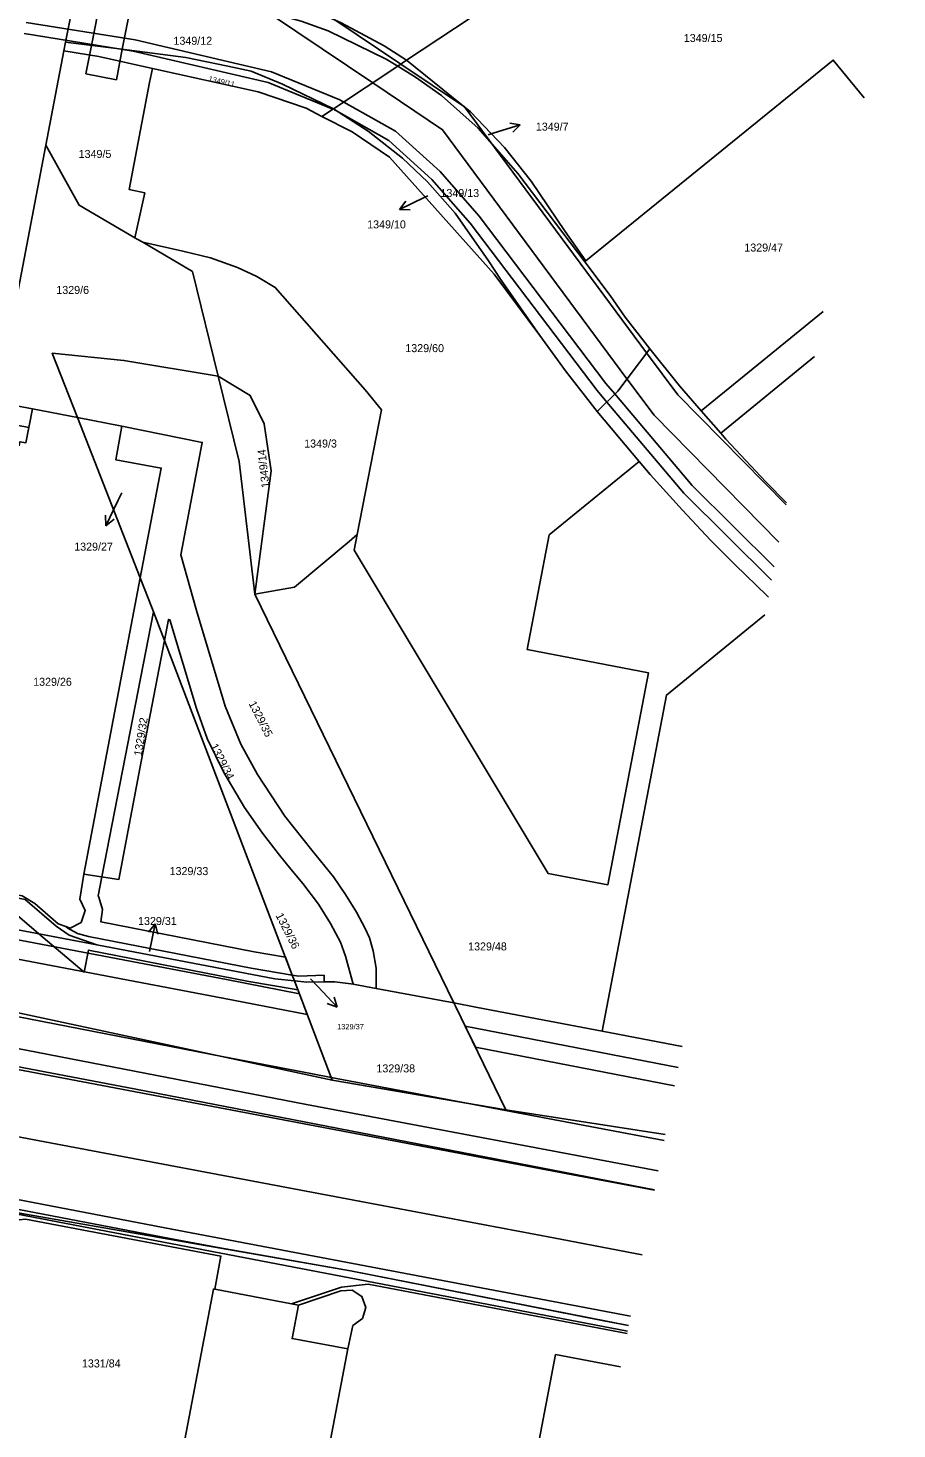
# Model space of a CAD drawing. Extents: x -601602 to -600882, y -1162594 to -1161950.
# Drawn here: x -600985.6 to -600893.3, y -1162422.3 to -1162273.6 of the extents above; entities that cross this region are included whole.
import ezdxf

# ---------------------------------------------------------------- set-up
doc = ezdxf.new("R2010")
doc.units = 0
for name, color, linetype in [('KN_Hranice parcel', 7, 'Continuous'), ('KN_Parcelní čísla', 7, 'Continuous'), ('KN_Pop  PČ popisy', 7, 'Continuous'), ('KN_Vnitřní kresba', 7, 'Continuous'), ('KN_Věcná břemena k části', 7, 'Continuous')]:
    doc.layers.add(name, color=color, linetype=linetype)

# ---------------------------------------------------------------- blocks, each defined once
blk = doc.blocks.new('1029_19')
at = {"layer": 'KN_Pop  PČ popisy'}
for p, q in [((0, 0), (-2.7, -1.32)), ((-2.7, -1.32), (-2.02, -0.43)), ((-2.7, -1.32), (-1.58, -1.33))]:
    blk.add_line(p, q, dxfattribs=at)
blk = doc.blocks.new('1029_44')
at = {"layer": 'KN_Pop  PČ popisy'}
for p, q in [((0, 0), (2.87, 0.88)), ((2.87, 0.88), (1.77, 1.06)), ((2.87, 0.88), (2.06, 0.11))]:
    blk.add_line(p, q, dxfattribs=at)
blk = doc.blocks.new('1029_53')
at = {"layer": 'KN_Pop  PČ popisy'}
for p, q in [((0, 0), (-1.32, -2.7)), ((-1.32, -2.7), (-1.33, -1.58)), ((-1.32, -2.7), (-0.43, -2.02))]:
    blk.add_line(p, q, dxfattribs=at)
blk = doc.blocks.new('1029_55')
at = {"layer": 'KN_Pop  PČ popisy'}
for p, q in [((0.57, 2.95), (-0.11, 2.06)), ((0, 0), (0.57, 2.95)), ((0.57, 2.95), (0.87, 1.87))]:
    blk.add_line(p, q, dxfattribs=at)
blk = doc.blocks.new('1029_56')
at = {"layer": 'KN_Pop  PČ popisy'}
for p, q in [((0, 0), (2.05, -2.19)), ((2.05, -2.19), (1.73, -1.12)), ((2.05, -2.19), (1, -1.8))]:
    blk.add_line(p, q, dxfattribs=at)

msp = doc.modelspace()

# ---------------------------------------------------------------- linework, layer by layer
at = {"layer": 'KN_Hranice parcel'}
for p, q in [((-600945.37, -1162276.99), (-600893.29, -1162242.43)), ((-600980.13, -1162267.57), (-600981.57, -1162275.06)), ((-600981.57, -1162275.06), (-600981.75, -1162275.98)), ((-600981.75, -1162275.98), (-600983.66, -1162285.99)), ((-600953.14, -1162282.15), (-600946.31, -1162277.62)), ((-600946.31, -1162277.62), (-600945.37, -1162276.99)), ((-600954.35, -1162282.95), (-600953.14, -1162282.15)), ((-600926.45, -1162298.39), (-600926.33, -1162298.3)), ((-600902.05, -1162308.45), (-600912.01, -1162316.57)), ((-600985.1, -1162314), (-600980.31, -1162314.93)), ((-600973.64, -1162331.94), (-600980.31, -1162314.93)), ((-600975.59, -1162315.84), (-600980.31, -1162314.93)), ((-600925.11, -1162314.27), (-600920.66, -1162319.58)), ((-600912.01, -1162316.57), (-600914.07, -1162314.2)), ((-600979.64, -1162363.4), (-600973.64, -1162331.94)), ((-600940.35, -1162377.09), (-600961.49, -1162333.68)), ((-600957.51, -1162374.13), (-600971.07, -1162338.59)), ((-600978.24, -1162370.92), (-600996.38, -1162367.46)), ((-600957.28, -1162374.74), (-600957.51, -1162374.13)), ((-600953.26, -1162385.27), (-600957.28, -1162374.74)), ((-600951.03, -1162375.09), (-600948.58, -1162375.55)), ((-600948.58, -1162375.55), (-600940.35, -1162377.09)), ((-600924.6, -1162380.1), (-600916.11, -1162381.72)), ((-600953.26, -1162385.27), (-600934.82, -1162388.45)), ((-600996.34, -1162397.68), (-600951.33, -1162405.52)), ((-600951.33, -1162405.52), (-600921.8, -1162411.34)), ((-600957.58, -1162409.04), (-600965.74, -1162407.49))]:
    msp.add_line(p, q, dxfattribs=at)
for points in [[(-600980.13, -1162267.57), (-600975.78, -1162268.36), (-600962.15, -1162271.32), (-600956.57, -1162272.84), (-600953.71, -1162273.86), (-600947.53, -1162276.88), (-600946.31, -1162277.62)], [(-600945.37, -1162276.99), (-600947.74, -1162275.47), (-600952.3, -1162273), (-600955.63, -1162271.53), (-600961.13, -1162269.66), (-600963.68, -1162269.01), (-600969.05, -1162268.07), (-600976.58, -1162267.13), (-600979.49, -1162266.77)], [(-600981.57, -1162275.06), (-600975.88, -1162275.78), (-600968.82, -1162276.68), (-600964.35, -1162277.6), (-600961.88, -1162278.16), (-600958.54, -1162279.52), (-600953.14, -1162282.15)], [(-600972.33, -1162277.85), (-600978.05, -1162276.59), (-600981.75, -1162275.98)], [(-600974.22, -1162295.84), (-600973.17, -1162291.07), (-600974.83, -1162290.7), (-600972.68, -1162279.36), (-600972.33, -1162277.85)], [(-600972.33, -1162277.85), (-600961.14, -1162280.33), (-600956.03, -1162282.09), (-600954.35, -1162282.95)], [(-600946.31, -1162277.62), (-600944.41, -1162278.77), (-600941.67, -1162280.74), (-600937.78, -1162284.21), (-600933.54, -1162289.01), (-600926.45, -1162298.39)], [(-600926.33, -1162298.3), (-600928.53, -1162295.18), (-600932.12, -1162289.81), (-600934.95, -1162286.26), (-600938.57, -1162282.47), (-600945.37, -1162276.99)], [(-600926.33, -1162298.3), (-600900.05, -1162276.97), (-600896.78, -1162280.98)], [(-600953.14, -1162282.15), (-600949.43, -1162284.52), (-600945.8, -1162287.38), (-600943.14, -1162289.9), (-600940.21, -1162293.21), (-600936.66, -1162298.28), (-600935.31, -1162300.33), (-600931.23, -1162306.23)], [(-600954.35, -1162282.95), (-600951.14, -1162284.6), (-600947.18, -1162287.26), (-600936.08, -1162299.69), (-600931.23, -1162306.23)], [(-600983.66, -1162285.99), (-600988.9, -1162313.29), (-600985.1, -1162314)], [(-600974.22, -1162295.84), (-600980.13, -1162292.38), (-600983.66, -1162285.99)], [(-600973.39, -1162296.32), (-600973.98, -1162295.98), (-600974.22, -1162295.84)], [(-600965.36, -1162310.53), (-600968.09, -1162299.42), (-600973.39, -1162296.32)], [(-600950.6, -1162327.36), (-600948.04, -1162314.1), (-600949.75, -1162312), (-600959.32, -1162301.1), (-600961.27, -1162299.95), (-600963.31, -1162298.98), (-600966.17, -1162297.95), (-600969.13, -1162297.27), (-600973.39, -1162296.32)], [(-600919.54, -1162307.62), (-600922.14, -1162304.25), (-600923.74, -1162301.98), (-600926.45, -1162298.39)], [(-600919.04, -1162396.97), (-600927.7, -1162395.33), (-600949.5, -1162391.18), (-600985.92, -1162384.31), (-601061.31, -1162370.08), (-601128.39, -1162357.28), (-601192.59, -1162345.07), (-601263.97, -1162331.56), (-601288.82, -1162326.8), (-601298.71, -1162324.89), (-601298.28, -1162322.82), (-601301.35, -1162321.33), (-601304.05, -1162318.46), (-601304.21, -1162314.16), (-601302.32, -1162304.33), (-601302.09, -1162303.45)], [(-600901.13, -1162303.65), (-600914.07, -1162314.2)], [(-600931.23, -1162306.23), (-600928.49, -1162309.95), (-600925.11, -1162314.27)], [(-600925.11, -1162314.27), (-600922.94, -1162312.11), (-600919.54, -1162307.62)], [(-600914.07, -1162314.2), (-600916.37, -1162311.55), (-600919.54, -1162307.62)], [(-600980.31, -1162314.93), (-600982.99, -1162308.1), (-600975.38, -1162308.86), (-600965.36, -1162310.53)], [(-600961.49, -1162333.68), (-600963.13, -1162319.59), (-600965.36, -1162310.53)], [(-600965.36, -1162310.53), (-600961.97, -1162312.57), (-600960.48, -1162315.59), (-600959.76, -1162320.57), (-600961.49, -1162333.68)], [(-600985.1, -1162314), (-600985.79, -1162317.61), (-600986.43, -1162317.49), (-600986.51, -1162317.92)], [(-600973.64, -1162331.94), (-600971.42, -1162320.3), (-600976.24, -1162319.4), (-600975.59, -1162315.84)], [(-600948.58, -1162375.55), (-600948.59, -1162373.39), (-600948.9, -1162371.54), (-600949.32, -1162370.16), (-600949.77, -1162369.19), (-600950.7, -1162367.46), (-600951.84, -1162365.56), (-600953.13, -1162363.69), (-600955.43, -1162360.88), (-600958.29, -1162357.25), (-600961.21, -1162352.82), (-600962.95, -1162349.61), (-600964.64, -1162345.58), (-600967.67, -1162335.43), (-600969.34, -1162329.5), (-600967.06, -1162317.56), (-600975.59, -1162315.84)], [(-600912.01, -1162316.57), (-600911.45, -1162317.22), (-600907.22, -1162321.76), (-600905.03, -1162323.97)], [(-600920.66, -1162319.58), (-600930.24, -1162327.39), (-600932.56, -1162339.57), (-600919.69, -1162342.03), (-600923.99, -1162364.53), (-600930.34, -1162363.34), (-600950.92, -1162329.01), (-600950.6, -1162327.36)], [(-600920.66, -1162319.58), (-600919.49, -1162320.97), (-600916.08, -1162324.76), (-600913.08, -1162327.93), (-600910.48, -1162330.57), (-600907.12, -1162333.83), (-600906.95, -1162333.99)], [(-600961.49, -1162333.68), (-600957.26, -1162332.93), (-600951.47, -1162328.09), (-600950.6, -1162327.36)], [(-601308.33, -1162348.97), (-601306.64, -1162340.12), (-601305.31, -1162336.84), (-601301.64, -1162333.66), (-601297.4, -1162332.52), (-601290.3, -1162333.64), (-601266.25, -1162338.24), (-601260.29, -1162339.36), (-601231.3, -1162344.87), (-601139.53, -1162362.21), (-601062.38, -1162376.91), (-600987.54, -1162391.11), (-600950.39, -1162398.12), (-600929.75, -1162402.03), (-600920.36, -1162403.85)], [(-600971.07, -1162338.59), (-600972.41, -1162335.08), (-600973.64, -1162331.94)], [(-600907.31, -1162335.87), (-600917.78, -1162344.4), (-600924.6, -1162380.1)], [(-600971.07, -1162338.59), (-600970.64, -1162336.36), (-600970.5, -1162336.4), (-600967.69, -1162345.81), (-600966.55, -1162349), (-600964.77, -1162352.6), (-600962.56, -1162356.35), (-600960.67, -1162359.07), (-600958.87, -1162361.39), (-600957.66, -1162362.87), (-600956.38, -1162364.42), (-600954.73, -1162366.6), (-600953.46, -1162368.65), (-600952.39, -1162370.65), (-600951.86, -1162372.11), (-600951.03, -1162375.09)], [(-600979.64, -1162363.4), (-600975.93, -1162363.99), (-600973.54, -1162351.45), (-600971.07, -1162338.59)], [(-601126.87, -1162349.73), (-601086.1, -1162356.8), (-600953.26, -1162385.27)], [(-600978.24, -1162370.92), (-600981.18, -1162369.89), (-600982.57, -1162368.92), (-600985.87, -1162366.11), (-600995.73, -1162364.23), (-600996.38, -1162367.46)], [(-600995.19, -1162363.7), (-600995.26, -1162364.04), (-600986.19, -1162365.73), (-600984.83, -1162366.53), (-600982.35, -1162368.69), (-600981.56, -1162368.97)], [(-600981.56, -1162368.97), (-600981.09, -1162369.13), (-600979.91, -1162368.54), (-600979.49, -1162367.27), (-600980.07, -1162366.07), (-600979.64, -1162363.4)], [(-600957.51, -1162374.13), (-600961.87, -1162373.39), (-600979.13, -1162370.02), (-600980.3, -1162369.7), (-600981.32, -1162369.14), (-600981.56, -1162368.97)], [(-600957.28, -1162374.74), (-600959.34, -1162374.53), (-600978.24, -1162370.92)], [(-600957.51, -1162374.13), (-600957.31, -1162374.17), (-600956.79, -1162374.23), (-600954.12, -1162374.15), (-600954.1, -1162374.85)], [(-600957.28, -1162374.74), (-600955.95, -1162374.87), (-600954.1, -1162374.85)], [(-600954.1, -1162374.85), (-600952.97, -1162374.84), (-600951.28, -1162375.04), (-600951.03, -1162375.09)], [(-600924.6, -1162380.1), (-600937.84, -1162377.56), (-600940.35, -1162377.09)], [(-600940.35, -1162377.09), (-600940.18, -1162377.44), (-600934.82, -1162388.45)], [(-600934.82, -1162388.45), (-600917.9, -1162391.07)], [(-600921.91, -1162411.94), (-600985.94, -1162399.66), (-600996.34, -1162397.68)], [(-600965.74, -1162407.49), (-600965.09, -1162403.96), (-600985.85, -1162400.03), (-600988.57, -1162400.32), (-600993.7, -1162402.13)], [(-600965.74, -1162407.49), (-600965.88, -1162407.47), (-600973.66, -1162448.32)], [(-600922.64, -1162415.72), (-600929.54, -1162414.43), (-600937.33, -1162455.26), (-600958.73, -1162451.15), (-600951.62, -1162413.83), (-600951.09, -1162411.34), (-600950.04, -1162410.59), (-600949.69, -1162409.41), (-600950.1, -1162408.24), (-600951.13, -1162407.58), (-600952.35, -1162407.66), (-600956.85, -1162409.18), (-600957.58, -1162409.04)], [(-600921.95, -1162412.17), (-600949.46, -1162406.96), (-600952.27, -1162407.27), (-600957.58, -1162409.04)]]:
    msp.add_lwpolyline(points, dxfattribs=at)
at = {"layer": 'KN_Pop  PČ popisy'}
for p, q in [((-600936.71, -1162284.91), (-600936.16, -1162284.73)), ((-600943.1, -1162291.37), (-600943.41, -1162291.53)), ((-600975.59, -1162322.91), (-600975.99, -1162323.71)), ((-600955.56, -1162374.51), (-600954.79, -1162375.34))]:
    msp.add_line(p, q, dxfattribs=at)
at = {"layer": 'KN_Vnitřní kresba'}
msp.add_lwpolyline([(-600956.85, -1162409.18), (-600957.52, -1162412.72), (-600951.62, -1162413.83)], dxfattribs=at)
at = {"layer": 'KN_Věcná břemena k části'}
for points in [[(-600905.07, -1162324.2), (-600916.57, -1162312.53), (-600919.88, -1162308.07), (-600939.23, -1162281.94), (-600945.99, -1162277.4), (-600952.98, -1162272.7), (-600958.47, -1162269.01), (-600976.98, -1162266.01), (-600977.19, -1162267.06), (-600978.83, -1162275.41), (-600979.42, -1162278.42), (-600976.18, -1162279.06), (-600975.55, -1162275.82), (-600974.36, -1162269.77), (-600959.71, -1162272.15), (-600948.96, -1162279.38), (-600941.55, -1162284.36), (-600921.96, -1162310.82), (-600919.09, -1162314.69), (-600905.83, -1162328.15)], [(-600906.33, -1162330.78), (-600915.04, -1162322.13), (-600923.25, -1162312.42), (-600924.2, -1162311.3), (-600937.66, -1162293.53), (-600941.81, -1162288.8), (-600946.55, -1162284.53), (-600952.04, -1162281.42), (-600952.45, -1162281.19), (-600959.7, -1162278.22), (-600974.17, -1162274.83), (-600985.77, -1162272.97)], [(-600985.99, -1162274.15), (-600975.7, -1162275.8), (-600974.41, -1162276.01), (-600960.06, -1162279.36), (-600953.19, -1162282.18), (-600953.14, -1162282.15), (-600952.97, -1162282.27), (-600952.81, -1162282.36), (-600947.25, -1162285.51), (-600942.67, -1162289.64), (-600938.6, -1162294.29), (-600925.14, -1162312.06), (-600924.11, -1162313.28), (-600915.92, -1162322.95), (-600906.61, -1162332.19)], [(-600985.79, -1162317.61), (-600985.48, -1162315.99), (-600989.53, -1162315.22)], [(-600919.03, -1162396.92), (-600974.13, -1162386.23), (-601268.36, -1162330.16)], [(-600986.68, -1162367.81), (-600984.4, -1162369.74), (-600978.24, -1162370.92), (-600959.34, -1162374.53), (-600957.28, -1162374.74), (-600957.51, -1162374.13), (-600958.24, -1162372.22), (-600961.56, -1162371.65), (-600977.84, -1162368.47), (-600977.67, -1162367.17), (-600978.03, -1162365.86), (-600978.12, -1162365.73), (-600977.72, -1162363.7), (-600972.23, -1162335.55), (-600972.41, -1162335.08), (-600973.64, -1162331.94), (-600979.64, -1162363.4), (-600980.07, -1162366.07), (-600979.49, -1162367.27), (-600979.91, -1162368.54), (-600981.09, -1162369.13), (-600981.56, -1162368.97), (-600982.35, -1162368.69), (-600984.83, -1162366.53), (-600986.19, -1162365.73)], [(-600918.02, -1162391.69), (-600938.8, -1162387.76), (-600953.26, -1162385.27), (-600953.36, -1162385.01), (-600955.37, -1162384.63), (-600964.96, -1162382.76), (-601051.29, -1162365.95), (-601087.38, -1162359.2), (-601128.25, -1162351.23), (-601195.49, -1162338.35)], [(-601196.15, -1162341.79), (-601130.52, -1162354.26), (-601131, -1162356.78), (-601127.76, -1162357.4), (-601127.28, -1162354.89), (-601088.02, -1162362.54), (-601051.91, -1162369.29), (-600955.99, -1162387.87), (-600918.65, -1162394.93)], [(-601192.59, -1162345.07), (-601128.39, -1162357.28), (-601061.31, -1162370.08), (-601057.74, -1162370.75), (-601052.4, -1162371.76), (-600985.92, -1162384.31), (-600949.5, -1162391.18), (-600927.7, -1162395.33), (-600919.04, -1162396.97)], [(-600921.6, -1162410.34), (-600970.3, -1162401.12), (-601068.63, -1162382.22), (-601072.9, -1162381.98), (-601140.82, -1162368.87), (-601207.09, -1162355.86)], [(-601164.77, -1162365.18), (-601141.49, -1162369.75), (-601141.53, -1162370), (-601142.19, -1162374.11), (-601141.2, -1162374.27), (-601140.55, -1162370.2), (-601140.51, -1162369.95), (-601073.02, -1162382.98), (-601068.76, -1162383.22), (-600970.49, -1162402.1), (-600965.2, -1162403.1), (-600951.33, -1162405.52), (-600924.42, -1162410.83), (-600921.79, -1162411.33)], [(-600916.54, -1162383.94), (-600939.16, -1162379.54), (-600938.06, -1162381.78), (-600916.91, -1162385.9)]]:
    msp.add_lwpolyline(points, dxfattribs=at)
for points in [[(-600955.92, -1162378.31), (-600956.75, -1162376.11), (-600964.48, -1162374.61), (-601029.83, -1162362.18), (-601127.47, -1162343.56), (-601127.27, -1162345.63), (-601030.21, -1162364.14), (-600964.86, -1162376.57)], [(-600957.28, -1162374.74), (-600959.34, -1162374.53), (-600978.24, -1162370.92), (-600984.4, -1162369.74), (-600979.62, -1162373.81), (-600979.16, -1162371.47), (-600962.13, -1162374.8), (-600957.51, -1162375.59), (-600956.92, -1162375.69)], [(-600953.36, -1162385.01), (-600953.26, -1162385.27), (-600938.8, -1162387.76)]]:
    msp.add_lwpolyline(points, close=True, dxfattribs=at)

# ---------------------------------------------------------------- block references
at = {"layer": 'KN_Pop  PČ popisy'}
for name, p in [('1029_44', (-600936.16, -1162284.73)), ('1029_19', (-600943.41, -1162291.53)), ('1029_53', (-600975.99, -1162323.71)), ('1029_55', (-600972.65, -1162371.64)), ('1029_56', (-600954.79, -1162375.34))]:
    msp.add_blockref(name, p, dxfattribs=at)

# ---------------------------------------------------------------- texts
at = {"layer": 'KN_Parcelní čísla'}
for s, height, p in [('1349/12', 0.85, (-600970.12, -1162275.34)), ('1349/15', 0.85, (-600915.93, -1162275.05)), ('1349/7', 0.85, (-600931.64, -1162284.46)), ('1349/5', 0.85, (-600980.19, -1162287.36)), ('1349/13', 0.85, (-600941.77, -1162291.51)), ('1349/10', 0.85, (-600949.55, -1162294.84)), ('1329/47', 0.85, (-600909.5, -1162297.3)), ('1329/6', 0.85, (-600982.56, -1162301.8)), ('1329/60', 0.85, (-600945.5, -1162307.98)), ('1349/3', 0.85, (-600956.24, -1162318.11)), ('1329/27', 0.85, (-600980.66, -1162329.06)), ('1329/26', 0.85, (-600985.02, -1162343.41)), ('1329/33', 0.85, (-600970.53, -1162363.51)), ('1329/31', 0.85, (-600973.88, -1162368.81)), ('1329/48', 0.85, (-600938.83, -1162371.51)), ('1329/37', 0.569, (-600952.74, -1162379.89)), ('1329/38', 0.85, (-600948.57, -1162384.46)), ('1331/84', 0.85, (-600979.84, -1162415.79))]:
    msp.add_text(s, height=height, dxfattribs=at).set_placement(p)
for s, height, rotation, p in [('1349/11', 0.569, 347, (-600966.44, -1162279.2)), ('1349/14', 0.85, 96, (-600959.92, -1162322.35)), ('1329/35', 0.85, 297, (-600962.16, -1162345.29)), ('1329/32', 0.85, 81, (-600973.49, -1162350.91)), ('1329/34', 0.85, 297, (-600966.24, -1162349.81)), ('1329/36', 0.85, 297, (-600959.3, -1162367.79))]:
    msp.add_text(s, height=height, rotation=rotation, dxfattribs=at).set_placement(p)

doc.saveas('drawing.dxf')
